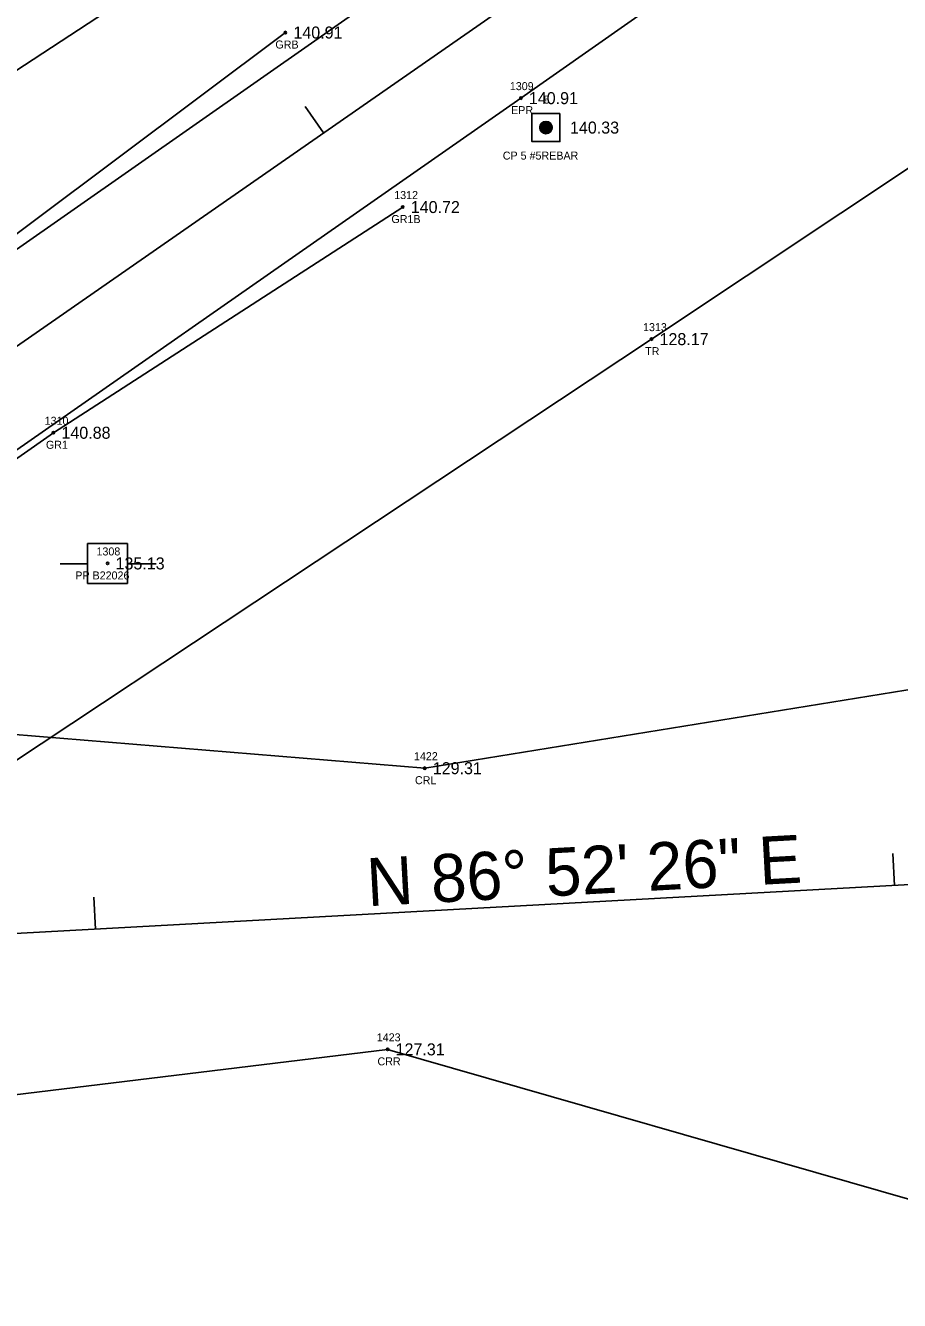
# Model space of a CAD drawing. Extents: x 2449052 to 2452984, y 1012343 to 1015262.
# Drawn here: x 2451147 to 2451256.3, y 1013885.3 to 1014044.7 of the extents above; entities that cross this region are included whole.
import ezdxf

# ---------------------------------------------------------------- set-up
doc = ezdxf.new("R2010")
doc.units = 0
for name, color, linetype in [('RD_EX_GuardRail', 7, 'Continuous'), ('RD_EX_GuardRail_txCode', 7, 'Continuous'), ('RD_EX_H2O', 7, 'Continuous'), ('RD_EX_H2O_txCode', 7, 'Continuous'), ('RD_EX_Road', 7, 'Continuous'), ('RD_EX_Road_txCode', 7, 'Continuous'), ('RD_EX_TX_GuardRail_ELEV', 7, 'Continuous'), ('RD_EX_TX_H2O_ELEV', 7, 'Continuous'), ('RD_EX_TX_Road_ELEV', 7, 'Continuous'), ('RD_EX_TX_VEG_ELEV', 7, 'Continuous'), ('RD_EX_UT', 7, 'Continuous'), ('RD_EX_UT_txCode', 7, 'Continuous'), ('RD_EX_VEG', 7, 'Continuous'), ('RD_EX_VEG_txCode', 7, 'Continuous'), ('RD_HC_Cl', 7, 'Continuous'), ('RD_HC_Data', 7, 'Continuous'), ('RD_HC_Data_Tic', 7, 'Continuous'), ('RD_HC_Survey', 7, 'Continuous'), ('RD_HC_Survey_ELEV', 7, 'Continuous'), ('RD_HC_Survey_txCode', 7, 'Continuous'), ('RD_SMD_Locator', 7, 'Continuous')]:
    doc.layers.add(name, color=color, linetype=linetype)

msp = doc.modelspace()

# ---------------------------------------------------------------- linework, layer by layer
at = {"layer": 'RD_EX_GuardRail'}
for points in [[(2451112.2, 1013994.9), (2451137.49, 1014012.36), (2451179.53, 1014043.8)], [(2451123.36, 1013974.73), (2451150.54, 1013993.78), (2451194.2, 1014021.99)]]:
    msp.add_lwpolyline(points, dxfattribs=at)
at = {"layer": 'RD_EX_H2O'}
for points in [[(2451076.27, 1013975.88), (2451136.08, 1013956.85), (2451196.95, 1013951.86), (2451272.49, 1013964.09), (2451374.53, 1013963.39), (2451437.08, 1013959.27), (2451486.99, 1013869.87), (2451511.13, 1013830.69)], [(2451013.97, 1013945.03), (2451057.54, 1013891.32), (2451091.48, 1013895.61), (2451128.22, 1013908.9), (2451192.3, 1013916.72), (2451258.16, 1013897.77), (2451360.62, 1013918.96), (2451380.18, 1013913.42), (2451411.99, 1013899.59), (2451448.35, 1013846.37), (2451473.38, 1013809.13)]]:
    msp.add_lwpolyline(points, dxfattribs=at)
at = {"layer": 'RD_EX_Road'}
for points in [[(2451113.37, 1013993.22), (2451114.95, 1013995.06), (2451198.45, 1014053.46), (2451277.07, 1014108.71), (2451354.65, 1014162.03), (2451438.1, 1014219.98), (2451516.17, 1014274.12), (2451595.76, 1014329.36), (2451675.91, 1014385.09), (2451754.57, 1014439.6), (2451832.18, 1014494.6), (2451911.27, 1014549.31), (2451991.99, 1014605.1), (2452071.96, 1014661.47), (2452153.31, 1014717.5), (2452234.82, 1014774.14), (2452317.24, 1014831.48), (2452344.94, 1014850.58)], [(2451124.98, 1013977.04), (2451208.96, 1014035.6), (2451289.19, 1014091.86), (2451364.64, 1014143.97), (2451446.58, 1014201.16), (2451526.53, 1014256.42), (2451607.39, 1014312.42), (2451687.4, 1014368.14), (2451765.64, 1014422.59), (2451815.07, 1014456.96), (2451825.17, 1014464.13), (2451844.11, 1014477.45), (2451922.22, 1014531.75), (2452002.87, 1014588.1), (2452083.85, 1014644.47), (2452165.65, 1014701.19), (2452246.96, 1014757.82), (2452328.43, 1014814.34), (2452355.9, 1014833.22)]]:
    msp.add_lwpolyline(points, dxfattribs=at)
at = {"layer": 'RD_EX_UT'}
for p, q in [((2451159.8, 1013979.96), (2451154.8, 1013979.96)), ((2451154.8, 1013979.96), (2451154.8, 1013974.96)), ((2451159.8, 1013974.96), (2451159.8, 1013979.96)), ((2451151.36, 1013977.4), (2451154.83, 1013977.4)), ((2451159.72, 1013977.4), (2451163.36, 1013977.4)), ((2451154.8, 1013974.96), (2451159.8, 1013974.96))]:
    msp.add_line(p, q, dxfattribs=at)
at = {"layer": 'RD_EX_VEG'}
for points in [[(2450511.25, 1013744.81), (2450612.22, 1013672.34), (2450883.9, 1013848.07), (2451091.43, 1014003.45), (2451271.45, 1014121.26), (2451583.45, 1014347.48), (2451819.08, 1014511.44), (2452219.54, 1014796.6), (2452332.78, 1014867.52)], [(2450813.9, 1013614.45), (2450759.99, 1013659.53), (2450819.72, 1013713.9), (2450939.16, 1013815.82), (2451225.29, 1014005.48), (2451628.56, 1014273.87), (2452372.22, 1014794.45)]]:
    msp.add_lwpolyline(points, dxfattribs=at)
at = {"layer": 'RD_HC_Cl'}
for p, q in [((2449680.91, 1012986.23), (2452350.19, 1014841.68)), ((2451086.18, 1013927.94), (2451352.92, 1013942.51))]:
    msp.add_line(p, q, dxfattribs=at)
at = {"layer": 'RD_HC_Data_Tic'}
for p, q in [((2451184.31, 1014031.26), (2451182.02, 1014034.54)), ((2451255.65, 1013937.2), (2451255.43, 1013941.19)), ((2451155.8, 1013931.74), (2451155.58, 1013935.74))]:
    msp.add_line(p, q, dxfattribs=at)
at = {"layer": 'RD_HC_Survey'}
for p, q in [((2451211.35, 1014031.75), (2451211.35, 1014032.1)), ((2451211.37, 1014031.66), (2451211.37, 1014032.19)), ((2451211.4, 1014031.6), (2451211.4, 1014032.25)), ((2451211.42, 1014031.55), (2451211.42, 1014032.3)), ((2451211.45, 1014031.51), (2451211.45, 1014032.34)), ((2451211.47, 1014031.48), (2451211.47, 1014032.37)), ((2451211.5, 1014031.44), (2451211.5, 1014032.41)), ((2451211.52, 1014031.41), (2451211.52, 1014032.44)), ((2451211.55, 1014031.39), (2451211.55, 1014032.46)), ((2451211.57, 1014031.36), (2451211.57, 1014032.49)), ((2451211.6, 1014031.34), (2451211.6, 1014032.51)), ((2451211.62, 1014031.32), (2451211.62, 1014032.53)), ((2451211.65, 1014031.3), (2451211.65, 1014032.55)), ((2451211.67, 1014031.28), (2451211.67, 1014032.56)), ((2451211.7, 1014031.27), (2451211.7, 1014032.58)), ((2451211.72, 1014031.25), (2451211.72, 1014032.6)), ((2451211.74, 1014031.24), (2451211.74, 1014032.61)), ((2451211.77, 1014031.23), (2451211.77, 1014032.62)), ((2451211.79, 1014031.22), (2451211.79, 1014032.63)), ((2451211.82, 1014031.21), (2451211.82, 1014032.64)), ((2451211.84, 1014031.2), (2451211.84, 1014032.65)), ((2451211.87, 1014031.19), (2451211.87, 1014032.66)), ((2451211.89, 1014031.18), (2451211.89, 1014032.67)), ((2451211.92, 1014031.18), (2451211.92, 1014032.67)), ((2451211.94, 1014031.17), (2451211.94, 1014032.68)), ((2451211.97, 1014031.17), (2451211.97, 1014032.68)), ((2451211.99, 1014031.16), (2451211.99, 1014032.69)), ((2451212.02, 1014031.16), (2451212.02, 1014032.69)), ((2451212.04, 1014031.16), (2451212.04, 1014032.69)), ((2451212.07, 1014031.16), (2451212.07, 1014032.69)), ((2451212.09, 1014031.16), (2451212.09, 1014032.69)), ((2451212.12, 1014031.16), (2451212.12, 1014032.69)), ((2451212.14, 1014031.16), (2451212.14, 1014032.69)), ((2451212.17, 1014031.16), (2451212.17, 1014032.69)), ((2451212.19, 1014031.16), (2451212.19, 1014032.69)), ((2451212.21, 1014031.16), (2451212.21, 1014032.68)), ((2451212.24, 1014031.17), (2451212.24, 1014032.68)), ((2451212.26, 1014031.17), (2451212.26, 1014032.68)), ((2451212.29, 1014031.18), (2451212.29, 1014032.67)), ((2451212.31, 1014031.19), (2451212.31, 1014032.66)), ((2451212.34, 1014031.19), (2451212.34, 1014032.66)), ((2451212.36, 1014031.2), (2451212.36, 1014032.65)), ((2451212.39, 1014031.21), (2451212.39, 1014032.64)), ((2451212.41, 1014031.22), (2451212.41, 1014032.63)), ((2451212.44, 1014031.23), (2451212.44, 1014032.61)), ((2451212.46, 1014031.25), (2451212.46, 1014032.6)), ((2451212.49, 1014031.26), (2451212.49, 1014032.59)), ((2451212.51, 1014031.28), (2451212.51, 1014032.57)), ((2451212.54, 1014031.29), (2451212.54, 1014032.56)), ((2451212.56, 1014031.31), (2451212.56, 1014032.54)), ((2451212.59, 1014031.33), (2451212.59, 1014032.52)), ((2451212.61, 1014031.35), (2451212.61, 1014032.5)), ((2451212.64, 1014031.37), (2451212.64, 1014032.47)), ((2451212.66, 1014031.4), (2451212.66, 1014032.45)), ((2451212.69, 1014031.43), (2451212.69, 1014032.42)), ((2451212.71, 1014031.46), (2451212.71, 1014032.39)), ((2451212.73, 1014031.49), (2451212.73, 1014032.36)), ((2451212.76, 1014031.53), (2451212.76, 1014032.32)), ((2451212.78, 1014031.58), (2451212.78, 1014032.27)), ((2451212.81, 1014031.63), (2451212.81, 1014032.22)), ((2451212.83, 1014031.7), (2451212.83, 1014032.15)), ((2451212.86, 1014031.81), (2451212.86, 1014032.04))]:
    msp.add_line(p, q, dxfattribs=at)
msp.add_lwpolyline([(2451213.85, 1014033.67), (2451210.35, 1014033.67), (2451210.35, 1014030.17), (2451213.85, 1014030.17)], close=True, dxfattribs=at)
msp.add_circle((2451212.1, 1014031.92), 0.769, dxfattribs=at)
at = {"layer": 'RD_SMD_Locator'}
for centre in [(2451179.53, 1014043.8), (2451208.96, 1014035.6), (2451212.1, 1014031.92), (2451194.2, 1014021.99), (2451225.29, 1014005.48), (2451150.54, 1013993.78), (2451157.3, 1013977.45), (2451196.95, 1013951.86), (2451192.3, 1013916.72)]:
    msp.add_circle(centre, 0.15, dxfattribs=at)

# ---------------------------------------------------------------- texts
at = {"layer": 'RD_EX_GuardRail_txCode'}
for s, p in [('GRB', (2451178.28, 1014041.8)), ('1312', (2451193.13, 1014022.99)), ('GR1B', (2451192.78, 1014019.99)), ('1310', (2451149.44, 1013994.78)), ('GR1', (2451149.6, 1013991.78))]:
    msp.add_text(s, height=1, dxfattribs=at).set_placement(p)
at = {"layer": 'RD_EX_H2O_txCode'}
for s, p in [('1422', (2451195.6, 1013952.86)), ('CRL', (2451195.72, 1013949.86)), ('1423', (2451190.95, 1013917.72)), ('CRR', (2451191.04, 1013914.72))]:
    msp.add_text(s, height=1, dxfattribs=at).set_placement(p)
at = {"layer": 'RD_EX_Road_txCode'}
for s, p in [('1309', (2451207.58, 1014036.6)), ('EPR', (2451207.74, 1014033.6))]:
    msp.add_text(s, height=1, dxfattribs=at).set_placement(p)
at = {"layer": 'RD_EX_TX_GuardRail_ELEV'}
for s, p in [('140.91', (2451180.53, 1014043.05)), ('140.72', (2451195.2, 1014021.24)), ('140.88', (2451151.54, 1013993.03))]:
    msp.add_text(s, height=1.5, dxfattribs=at).set_placement(p)
at = {"layer": 'RD_EX_TX_H2O_ELEV'}
for s, p in [('129.31', (2451197.95, 1013951.11)), ('127.31', (2451193.3, 1013915.97))]:
    msp.add_text(s, height=1.5, dxfattribs=at).set_placement(p)
at = {"layer": 'RD_EX_TX_Road_ELEV'}
msp.add_text('140.91', height=1.5, dxfattribs=at).set_placement((2451209.96, 1014034.85))
at = {"layer": 'RD_EX_TX_VEG_ELEV'}
msp.add_text('128.17', height=1.5, dxfattribs=at).set_placement((2451226.29, 1014004.73))
at = {"layer": 'RD_EX_UT_txCode'}
for s, p in [('1308', (2451155.92, 1013978.45)), ('PP B22026', (2451153.27, 1013975.45))]:
    msp.add_text(s, height=1, dxfattribs=at).set_placement(p)
at = {"layer": 'RD_EX_VEG_txCode'}
for s, p in [('1313', (2451224.23, 1014006.48)), ('TR', (2451224.49, 1014003.48))]:
    msp.add_text(s, height=1, dxfattribs=at).set_placement(p)
at = {"layer": 'RD_HC_Data'}
msp.add_text('N 86%%d 52\' 26" E', height=6, rotation=3.126, dxfattribs=at).set_placement((2451189.85, 1013934.6))
at = {"layer": 'RD_HC_Survey_ELEV'}
for s, p in [('140.33', (2451215.1, 1014031.17)), ('135.13', (2451158.3, 1013976.7))]:
    msp.add_text(s, height=1.5, dxfattribs=at).set_placement(p)
at = {"layer": 'RD_HC_Survey_txCode'}
for s, p in [('5', (2451211.81, 1014034.92)), ('CP 5 #5REBAR', (2451206.7, 1014027.92))]:
    msp.add_text(s, height=1, dxfattribs=at).set_placement(p)

doc.saveas('drawing.dxf')
